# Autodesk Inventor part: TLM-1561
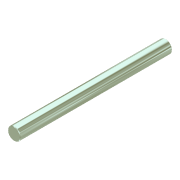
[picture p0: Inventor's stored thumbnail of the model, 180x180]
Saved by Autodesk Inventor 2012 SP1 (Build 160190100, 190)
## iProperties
Shininess: 60.0
Length Units: 11269
Angle Units: 11279
Time Units: 11290
Mass Units: 11283
Length Display Precision: 3
Angle Display Precision: 2
Compacted: True
Created: 2000-06
Part Number: TLM-1561
Material: Stainless Steel, Austenitic
Description: THOMSON SHAFT 1.00" DIA X 12.0" LONG
Vendor: REID TOOL
Document SubType Name: Modeling
Designer: Ron
Density: 8.03 g/cm^3
Density: 8.03
Volumn: 227.9406635355751
Area: 368.2572904781091
PropertySet Name: Model Information
Control State: 0
Master: False
Checked Out: False
Author: Ron
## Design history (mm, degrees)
node "Extrusion1" dims "d1" = 304.8, "d2" = 0
  sketch "Sketch1"
    geometry: C1 r 12.7 at (0, 0); 1 further point
    constraints: 1 centre point, 1 coincident
    dimensions: "d0" = 25.4 diameter of C1
node "Chamfer1" dims "d3" = 1, "d4" = 1, "d5" = 45 deg
body "Solid1"
